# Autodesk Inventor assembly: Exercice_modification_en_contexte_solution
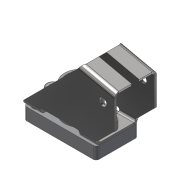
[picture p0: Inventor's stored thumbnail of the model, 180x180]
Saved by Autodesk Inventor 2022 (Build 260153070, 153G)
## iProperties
Created: 2018-06
Part Number: Exercice_modification_en_contexte_solution
Material: Générique
Document SubType Name: Assembly
Designer: Fabian Perrée
Mass: 105.136 g
Surface Area: 173.547 cm^2
Volume: 19.7524 cm^3
Density: 5.32267 g/cm^3
Author: Fabian Perrée
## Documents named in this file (5)
- C:\Users\Fabian\Google Drive\01_Giup\01_Clients\07_ENI\Manuscrit\Fichiers_exercice\Chapitre_06\Exercice_modification_en_contexte\Exercice_modification_en_contexte_solution.iam
- C:\Users\Fabian\Google Drive\01_Giup\01_Clients\07_ENI\Manuscrit\Fichiers_exercice\Chapitre_06\Exercice_modification_en_contexte\Composants\Etrier_tole.ipt
- C:\Users\Fabian\Google Drive\01_Giup\01_Clients\07_ENI\Manuscrit\Fichiers_exercice\CC\ISO 4762 - M5 x 8ISO.ipt
- C:\Users\Fabian\Google Drive\01_Giup\01_Clients\07_ENI\Manuscrit\Fichiers_exercice\Chapitre_06\Exercice_modification_en_contexte\Composants\Bille_18.ipt
- C:\Users\Fabian\Google Drive\01_Giup\01_Clients\07_ENI\Manuscrit\Fichiers_exercice\Chapitre_06\Exercice_modification_en_contexte\Composants\Chapeau_capteur_solution.ipt
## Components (5 placed, 4 different names)
1. Etrier_tole:1 — Logement:3, Logement:4
2. Chapeau_capteur_solution:1 — Logement:3, Logement:4
3. Bille_18:1
4. ISO 4762 M5 x 8:1
5. ISO 4762 M5 x 8:2
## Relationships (2: Insert 2)
- Logement:3 [Insert]: Etrier_tole:1 ↔ Chapeau_capteur_solution:1
- Logement:4 [Insert]: Etrier_tole:1 ↔ Chapeau_capteur_solution:1
